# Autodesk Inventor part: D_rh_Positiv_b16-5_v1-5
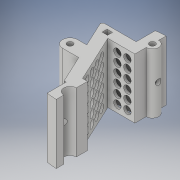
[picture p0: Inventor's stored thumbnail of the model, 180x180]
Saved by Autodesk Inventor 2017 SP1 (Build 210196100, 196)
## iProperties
Part Number: D_rh_Positiv_b16-5_v1-5
Material: Generisch
Document SubType Name: Modeling
Designer: haesner
Density: 1 g/cm^3
Appearance: Vorgabe
Part Number: D_rh_Positiv_b16-5_v1-5_3D-Druck
Author: haesner
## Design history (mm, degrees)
sketch "Skizze1"
  geometry: L1 (0, 9.5)-(-10.86, 9.5); L2 (-10.86, 9.5)-(-2, -9.5); L3 (-2, -9.5)-(0, -9.5); L4 (0, 22)-(0, 19); L5 (0, 14)-(0, 9.5); L6 (0, -22)-(0, -19); L7 (0, -9.5)-(0, -14); L8 (-26.9, 0)-(7.4, 0) reference; L9 (0, -30.8)-(0, 30.8) reference; C1 r 1.15 at (-16.5, 0); C2 r 1.15 at (0, 16.5); A1 r 22 centre (0, 0) between (0, 22) and (0, -22); A2 r 2.5 centre (0, 16.5) between (0, 14) and (0, 19); A3 r 2.5 centre (0, -16.5) between (0, -14) and (0, -19); 1 further point
  constraints: 14 end point, 6 point on circle, 5 centre point, 4 collinear, 4 point on line, 2 coincident, 2 equal radius, 1 horizontal, 1 parallel, 1 other
  dimensions: "d1" = 22 radius of A1; "d4" = 2.3 diameter of C2; "d5" = 2.5 radius of A3; "d6" = 16.5 distance from line of L8 A3.centre; "d7" = 16.5 distance from line of L8 A2.centre (= d6); "d8" = 16.5 distance from line of L9 C1.centre (= d6); "d10" = 19 distance between parallel lines of L3 L1; "d140" = 2 distance of L2.end L3.end; "d141" = 25 deg angle of L2 L9
extrude "Extrusion1" new body sketch "Skizze1" distance "d11" = 3; taper "d12" = 0 deg
sketch "Skizze12"
  geometry: L1 (-4, 21.633)-(-4, 14); L2 (0, 19)-(0, 22); L3 (0, -14)-(0, -9.5) reference; L4 (0, -9.5)-(-2, -9.5) reference; L5 (-2, -9.5)-(-10.86, 9.5) reference; L6 (-10.86, 9.5)-(0, 9.5) reference; L7 (0, 9.5)-(0, 14) reference; L8 (-4, 14)-(-16.971, 14); L9 (-17.569, 13.241)-(-4.867, -14); L10 (0, -22)-(0, -19) reference; L11 (-4.867, -14)-(-4, -14); L12 (-4, -14)-(-4, -21.633); L13 (-16.5, -3)-(-9.996, -3); L14 (-16.5, 3)-(-12.794, 3); L15 (-26.9, 0)-(7.402, 0) reference; C1 r 1.15 at (0, 16.5); C2 r 1.15 at (0, 16.5); C3 r 1.15 at (-16.5, 0) reference; A1 r 2.5 centre (0, 16.5) between (0, 14) and (0, 19); A2 r 22 centre (0, 0) between (-4, -21.633) and (0, -22); A3 r 22 centre (0, 0) between (0, 22) and (-4, 21.633); A4 r 2.5 centre (0, -16.5) between (0, -14) and (0, -19) reference; A5 r 22 centre (0, 0) between (0, 22) and (0, -22) reference; A6 r 22 centre (0, 0) between (-16.971, 14) and (-17.569, 13.241); A7 r 3 centre (-16.5, 0) between (-16.5, 3) and (-16.5, -3); 3 further points
  constraints: 16 end point, 10 point on circle, 7 centre point, 5 coincident, 4 horizontal, 2 point on line, 2 vertical, 1 concentric, 1 midpoint, 1 parallel, 1 other
  dimensions: "d113" = 4 distance between parallel lines of L1 L2; "d142" = 4.5 distance between parallel lines of L6 L8; "d143" = 4.5 distance between parallel lines of L5 L9 (derived); "d145" = 4 distance between parallel lines of L10 L12 (derived); "d146" = 4.5 distance from line of point (-4.433, -14) L4 (derived); "d168" = 3 radius of A7; "d169" = 6 distance between parallel lines of L13 L14
extrude "Extrusion11" join sketch "Skizze12" distance "d109" = 18; taper "d110" = 0 deg
sketch "Skizze14"
  geometry: L1 (0, -22)-(0, -19) reference; L2 (0, -14)-(0, -9.5) reference; L3 (0, -9.5)-(-2, -9.5) reference; L4 (-2, -9.5)-(-10.86, 9.5) reference; L5 (-10.86, 9.5)-(0, 9.5) reference; L6 (0, 9.5)-(0, 14) reference; L7 (0, 19)-(0, 22) reference; C1 r 1.15 at (0, 16.5) reference; C2 r 1.15 at (-16.5, 0) reference; A1 r 22 centre (0, 0) between (-4, 21.633) and (-16.971, 14) reference; A2 r 22 centre (0, 0) between (0, 22) and (-4, 21.633) reference; A3 r 22 centre (0, 0) between (-16.971, 14) and (-17.569, 13.241) reference; A4 r 22 centre (0, 0) between (-17.569, 13.241) and (-4, -21.633) reference; A5 r 22 centre (0, 0) between (-4, -21.633) and (0, -22) reference; A6 r 2.5 centre (0, -16.5) between (0, -14) and (0, -19) reference; A7 r 2.5 centre (0, 16.5) between (0, 14) and (0, 19) reference; 1 further point
extrude "Extrusion14" join sketch "Skizze14" distance "d151" = 3; taper "d152" = 0 deg
sketch "Skizze7"
  geometry: L1 (6.6, -5.199)-(6.6, -9.199); L2 (6.6, -9.199)-(10.2, -9.199); L3 (10.2, -9.199)-(10.2, -5.199); L4 (10.2, -5.199)-(13.8, -5.199); L5 (13.8, -5.199)-(13.8, -9.199); L6 (13.8, -9.199)-(17.4, -9.199); L7 (17.4, -9.199)-(17.4, -5.199); L8 (17.4, -5.199)-(21, -5.199); L9 (21, -5.199)-(21, -9.199); L10 (21, -9.199)-(21, -13.199); L11 (21, -13.199)-(21, -17.199); L12 (21, -17.199)-(17.4, -17.199); L13 (17.4, -17.199)-(17.4, -13.199); L14 (17.4, -13.199)-(13.8, -13.199); L15 (13.8, -13.199)-(13.8, -17.199); L16 (10.2, -17.199)-(10.2, -13.199); L17 (6.6, -13.199)-(6.6, -17.199); L18 (10.2, -17.199)-(13.8, -17.199); L19 (10.2, -13.199)-(6.6, -13.199); L20 (6.6, -5.199)-(3, -5.199); L21 (3, -5.199)-(3, -9.199); L22 (6.6, -17.199)-(3, -17.199); L23 (3, -17.199)-(3, -13.199); L24 (24, -44.241)-(24, 26.083) reference; L25 (28.2, -13.199)-(-1.2, -13.199) reference
  constraints: 46 end point, 20 point on line, 10 equal length, 10 perpendicular, 3 horizontal, 2 vertical, 1 collinear
  dimensions: "d49" = 4 distance between parallel lines of L6 L14; "d50" = 4 distance of L17.start L17.end; "d59" = 3.6 distance of L7.end L8.end; "d153" = 3 distance between parallel lines of L24 L10
hole "Bohrung1" sketch "Skizze7" diameter "d52" = 3; stored, may be unused: countersink angle "d56" = 90 deg, drill point angle "d58" = 118 deg; dims "d53" = 6, "d54" = 4, "d55" = 2, "d57" = 1.8
sketch "Skizze8"
  geometry: L1 (7.86, 6.6)-(3.86, 6.6); L2 (3.86, 6.6)-(3.86, 10.2); L3 (3.86, 10.2)-(7.86, 10.2); L4 (7.86, 10.2)-(7.86, 13.8); L5 (7.86, 13.8)-(3.86, 13.8); L6 (3.86, 13.8)-(3.86, 17.4); L7 (3.86, 17.4)-(7.86, 17.4); L8 (7.86, 17.4)-(7.86, 21); L9 (7.86, 21)-(3.86, 21); L10 (7.86, 6.6)-(7.86, 3); L11 (7.86, 3)-(3.86, 3); L12 (-34.813, 0)-(25.673, 0) reference; L13 (10.86, -33.6)-(10.86, 33.6) reference; 5 further points; 2 other entities
  constraints: 22 end point, 9 equal length, 4 perpendicular, 3 parallel, 2 horizontal, 2 vertical, 6 other
  dimensions: "d60" = 4 distance of L1.start L1.end; "d61" = 3.6 distance of L1.end L2.end; "d62" = 3 dimension on L9; "d139" = 2.5 dimension on L4; "d154" = 3 distance between parallel lines of L12 L11; "d155" = 3 distance between parallel lines of L13 L8
hole "Bohrung2" sketch "Skizze8" diameter "d64" = 3; stored, may be unused: countersink angle "d68" = 90 deg, drill point angle "d70" = 118 deg; dims "d65" = 6, "d66" = 4, "d67" = 2, "d69" = 1.8
sketch "Skizze6"
  geometry: L1 (3.911, -12.5)-(1, -12.5); L2 (1, -12.5)-(1, -10.5); L3 (0, -30.8)-(0, 30.8) reference; L4 (2.637, -10.5)-(11.963, 9.5); L5 (2.637, -10.5)-(1, -10.5); L6 (0, -9.5)-(2, -9.5) reference; L7 (10.86, 10.5)-(1, 10.5); L8 (1, 10.5)-(1, 12.5); L9 (10.86, 9.5)-(0, 9.5) reference; L10 (2, -9.5)-(10.86, 9.5) reference; L11 (10.86, 10.5)-(10.86, 12.5); L12 (11.963, 9.5)-(14.17, 9.5); L13 (10.86, 12.5)-(1, 12.5); L14 (14.17, 9.5)-(3.911, -12.5); 1 further point
  constraints: 21 end point, 4 horizontal, 2 perpendicular, 2 vertical, 1 collinear, 1 point on line
  dimensions: "d41" = 1 distance between parallel lines of L3 L2; "d130" = 1 distance between parallel lines of L6 L5; "d131" = 1 distance between parallel lines of L3 L8 (derived); "d133" = 2 distance between parallel lines of L5 L1; "d134" = 1 distance between parallel lines of L9 L7 (derived); "d135" = 1 distance between parallel lines of L10 L4 (derived); "d172" = 2 distance between parallel lines of L14 L4 (derived); "d173" = 2 distance between parallel lines of L7 L13 (derived)
extrude "Extrusion6" cut sketch "Skizze6" distance "d39" = 23; taper "d40" = 0 deg
sketch "Skizze15"
  geometry: L1 (4, 14)-(4, 21.633) reference; L2 (16.971, 14)-(4, 14) reference; L3 (4, -21.633)-(4, -14) reference; L4 (4, -14)-(4.867, -14) reference; L5 (16.5, 3)-(12.794, 3) reference; L6 (9.996, -3)-(16.5, -3) reference; L7 (12.794, 3)-(17.569, 13.241) reference; L8 (4.867, -14)-(9.996, -3) reference; A1 r 22 centre (0, 0) between (0, -22) and (0, 22) reference; A2 r 22 centre (0, 0) between (4, -21.633) and (17.569, 13.241) reference; A3 r 3 centre (16.5, 0) between (16.5, -3) and (16.5, 3) reference; 1 further point
sketch "Skizze16"
  geometry: L1 (12, 2.5)-(12, -30.5); L2 (-4.8, -14)-(28.8, -14) reference; L3 (0, -44.8)-(0, 16.8) reference; 1 further point
  constraints: 2 end point, 1 symmetric about line, 1 vertical
  dimensions: "d159" = 12 distance between parallel lines of L3 L1; "d160" = 33 distance of L1.start L1.end
hole "Bohrung4" sketch "Skizze16" at (12, 2.5), (12, -30.5) diameter "d161" = 2.3; stored, may be unused: countersink angle "d165" = 90 deg, drill point angle "d167" = 118 deg; dims "d162" = 6, "d163" = 4, "d164" = 2, "d166" = 8
extrude "Extrusion16" cut sketch "Skizze15" distance "d170" = 30; taper "d171" = 0 deg
sketch "Skizze17"
  geometry: L1 (14.17, 10.5)-(11.963, 10.5); L2 (11.963, 10.5)-(11.963, 12.5); L3 (11.963, 12.5)-(14.17, 12.5); L4 (14.17, 12.5)-(14.17, 10.5); L5 (11.963, 9.5)-(14.17, 9.5) reference; L6 (10.86, 12.5)-(10.86, 10.5) reference; 1 further point
  constraints: 8 end point, 4 parallel, 2 point on line, 1 horizontal, 1 perpendicular
extrude "Extrusion17" cut sketch "Skizze17" distance "d174" = 40; taper "d175" = 0 deg
sketch "Skizze18"
  geometry: L1 (14.17, 9.5)-(11.963, 9.5); L2 (11.963, 9.5)-(11.963, 10.5); L3 (11.963, 10.5)-(14.17, 10.5); L4 (14.17, 10.5)-(14.17, 9.5); L5 (11.963, 10.5)-(10.86, 10.5); L6 (10.86, 10.5)-(10.86, 12.5); L7 (10.86, 12.5)-(11.963, 12.5); L8 (11.963, 12.5)-(11.963, 10.5); L9 (11.963, 9.5)-(14.17, 9.5) reference; L10 (14.17, 10.5)-(11.963, 10.5) reference; L11 (10.86, 12.5)-(10.86, 10.5) reference; L12 (11.963, 10.5)-(11.963, 12.5) reference; 1 further point
  constraints: 16 end point, 4 collinear, 4 parallel, 4 point on line, 2 horizontal, 2 perpendicular
extrude "Extrusion18" cut sketch "Skizze18" distance "d176" = 8; taper "d177" = 0 deg
sketch "Skizze13"
  geometry: L1 (9, 38.133)-(9, 5.133); L2 (-7.2, 21.633)-(22.2, 21.633) reference; L3 (-3, -9.167)-(-3, 52.433) reference; 1 further point
  constraints: 2 end point, 1 symmetric about line, 1 vertical
  dimensions: "d114" = 12 distance between parallel lines of L3 L1; "d115" = 33 distance of L1.start L1.end
hole "Bohrung3" sketch "Skizze13" at (9, 38.133), (9, 5.133) diameter "d116" = 2.3; stored, may be unused: countersink angle "d120" = 90 deg, drill point angle "d122" = 118 deg; dims "d117" = 6, "d118" = 4, "d119" = 2, "d121" = 8
sketch "Skizze9"
  geometry: L1 (-4, -20.274)-(-14, -14.5); L2 (-14, -14.5)-(-4, -14.5); L3 (-6.459, 16.5)-(-12.737, 3.038); L4 (-12.737, 3.038)-(-19.081, 5.996); L5 (0, 16.5)-(-33.947, 16.5); L6 (-6.459, 16.5)-(-9.459, 16.5); L7 (-19.081, 5.996)-(-9.459, 16.5); L8 (-4, -14.5)-(-4, -20.274); L9 (-40.966, 0)-(8.169, 0) reference; L10 (0, 25.235)-(0, -27.858) reference; L11 (-1, -12.5)-(-15.569, -12.5) reference; C1 r 1.15 at (0, 16.5) reference; 6 further points; 1 other entity
  constraints: 16 end point, 2 point on line, 1 coincident, 1 horizontal, 1 perpendicular, 1 vertical, 1 other
  dimensions: "d71" = 7 distance of L3.end L4.end; "d72" = 3 distance of L6.end L3.start; "d78" = 30 deg angle of L2 L1; "d100" = 10 distance of L1.end L2.end; "d123" = 4 distance between parallel lines of L10 L8; "d124" = 2 distance between parallel lines of L2 L11; "d125" = 4 dimension on L3
extrude "Extrusion7" cut sketch "Skizze9" distance "d79" = 30; taper "d80" = 0 deg
fillet "Rundung8" dims "d127" = 1
node "Volumenkörper1"
other parameters: "d29" = 1, "d36" = 2, "d112" = 4
